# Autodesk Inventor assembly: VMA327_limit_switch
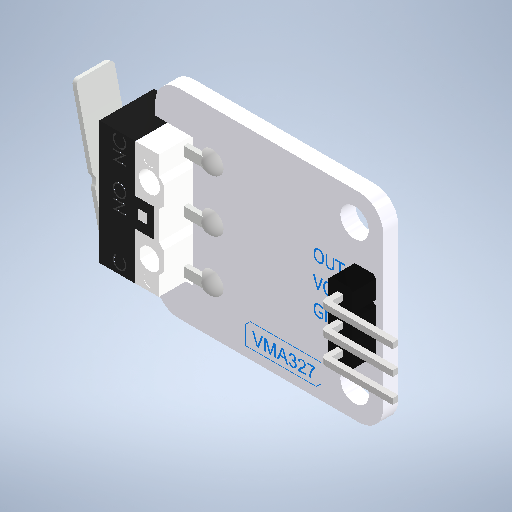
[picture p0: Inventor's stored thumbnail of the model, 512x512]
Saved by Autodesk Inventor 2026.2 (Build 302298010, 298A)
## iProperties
Created: 2023-02
Part Number: VMA327_limit_switch
Document SubType Name: Assembly
Designer: mel
Title: D:\Documenten\Inventor\Project files\Strijkkralen sorteermachine\VMA327_limit_switch.stp
Author: Gebruiker
Sending System: Autodesk Inventor 2020
Preprocessor: ST-DEVELOPER v18
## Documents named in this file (6)
- D:\travail\année 2026-2027\1 sti2d IT\poubelle à verre\vma327-limit-switch-1.snapshot.2\VMA327_limit_switch\VMA327_limit_switch\VMA327_limit_switch.iam
- D:\travail\année 2026-2027\1 sti2d IT\poubelle à verre\vma327-limit-switch-1.snapshot.2\VMA327_limit_switch\VMA327_limit_switch\VMA327_PCB.ipt
- D:\travail\année 2026-2027\1 sti2d IT\poubelle à verre\vma327-limit-switch-1.snapshot.2\VMA327_limit_switch\VMA327_limit_switch\Limit_Switch.ipt
- D:\travail\année 2026-2027\1 sti2d IT\poubelle à verre\vma327-limit-switch-1.snapshot.2\VMA327_limit_switch\VMA327_limit_switch\Haakse_PCB_connector.ipt
- D:\travail\année 2026-2027\1 sti2d IT\poubelle à verre\vma327-limit-switch-1.snapshot.2\VMA327_limit_switch\VMA327_limit_switch\Soldeerpunt.ipt
- D:\travail\année 2026-2027\1 sti2d IT\poubelle à verre\vma327-limit-switch-1.snapshot.2\VMA327_limit_switch\VMA327_limit_switch\Soldeerdruppel.ipt
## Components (9 placed, 5 different names)
1. VMA327_PCB:1
2. Limit_Switch:1
3. Haakse_PCB_connector:1
4. Soldeerpunt:1
5. Soldeerpunt:2
6. Soldeerpunt:3
7. Soldeerdruppel:1
8. Soldeerdruppel:2
9. Soldeerdruppel:3
